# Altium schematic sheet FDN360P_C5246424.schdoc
size 127 x 101 mm
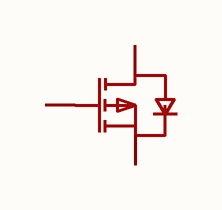
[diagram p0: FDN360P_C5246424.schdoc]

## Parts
Q?  fdn360p_c5246424  [SOT-23-3_L2.9-W1.3-P1.90-LS2.4-BR]  (value not drawn)

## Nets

Not connected (* = marked no-connect by the designer): Q? 1(G) 2(S) 3(D)

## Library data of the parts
Q? = fdn360p_c5246424: 漏源电压(Vdss):30V;连续漏极电流(Id):2A;导通电阻(RDS(on)):60mΩ@4.5V,2.2A;耗散功率(Pd):1.2W;阈值电压(Vgs(th)):3V;; Manufacturer: TECH PUBLIC(台舟); AddInBom: yes; ModelId: c62791f0466c4ae2a892c056b845b0ca; ModelName: SOT-23-3P_L2.9-W1.3-H1.0-LS2.4-P0.95; ModelTransform: 98.425,114.173,0,180,0,0,0.0005,-0.0005,0; Drain to Source Voltage: 30V; Current - Continuous Drain(Id): 2A; Pd - Power Dissipation: 1.2W; Gate Threshold Voltage (Vgs(th)): 3V; Input Capacitance(Ciss): 300pF@10V; Output Capacitance(Coss): 145pF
